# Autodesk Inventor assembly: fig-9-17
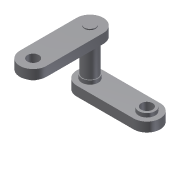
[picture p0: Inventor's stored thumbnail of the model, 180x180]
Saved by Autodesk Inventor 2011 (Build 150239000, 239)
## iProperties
Shininess: 64.0
Length Units: 11269
Angle Units: 11279
Time Units: 11290
Mass Units: 11283
Length Display Precision: 3
Angle Display Precision: 2
Created: 2002-01
Part Number: fig-9-17
Document SubType Name: Assembly
Designer: ***
Density: 0.0
Volumn: 0.0
Area: 0.0
PropertySet Name: Model Information
Control State: 0
Master: False
Checked Out: False
Author: ***
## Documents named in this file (3)
- C:\Users\CADSoft\Desktop\part files\c09-inv-2011-prt\fig-9-17.iam
- C:\Users\CADSoft\Desktop\inventor\c09-inv-2010-prt\c09\Part5.ipt
- C:\Users\CADSoft\Desktop\inventor\c09-inv-2010-prt\c09\Part6.ipt
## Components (3 placed, 2 different names)
1. Part5:1 — Insert:1
2. Part6:1 — Insert:1, Insert:2
3. Part5:2 — Insert:2
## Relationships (2: Insert 2)
- Insert:1: Part5:1 ↔ Part6:1
- Insert:2: Part6:1 ↔ Part5:2
